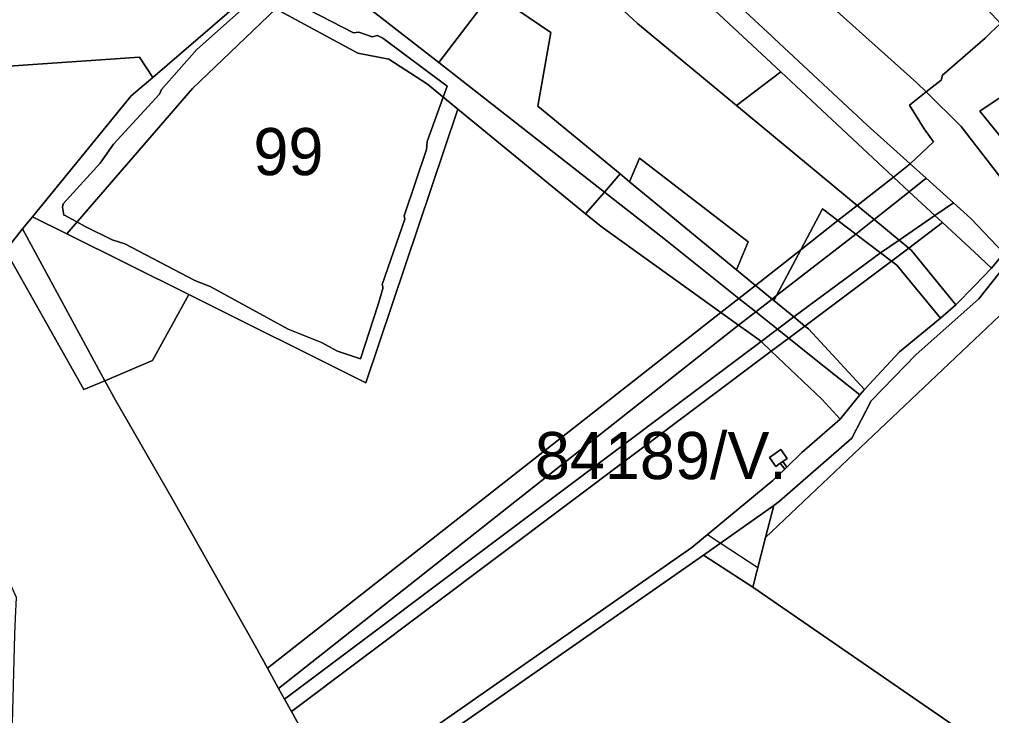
# Model space of a CAD drawing. Extents: x -477304 to -465429, y -1159113 to -1149210.
# Drawn here: x -474718.2 to -474408.5, y -1155444.6 to -1155222.8 of the extents above; entities that cross this region are included whole.
import ezdxf

# ---------------------------------------------------------------- set-up
doc = ezdxf.new("R2010")
doc.units = 0
for name, color, linetype in [('BPEJ_s', 7, 'Continuous'), ('ostatni_s', 7, 'Continuous'), ('PUPFL_s', 7, 'Continuous'), ('trav_porost_s', 7, 'Continuous')]:
    doc.layers.add(name, color=color, linetype=linetype)

msp = doc.modelspace()

# ---------------------------------------------------------------- linework, layer by layer
at = {"layer": 'BPEJ_s'}
for points in [[(-474633.02, -1155216.01), (-474611.78, -1155227.06), (-474610.08, -1155226.85), (-474605.83, -1155228.34), (-474604.12, -1155227.91), (-474602.42, -1155228.76), (-474582.01, -1155244.07), (-474582.86, -1155246.41), (-474583.26, -1155247.51), (-474588.39, -1155261.72), (-474588.6, -1155264.27), (-474595.62, -1155285.32), (-474595.41, -1155286.39), (-474602.64, -1155307.23), (-474602.51, -1155307.96), (-474602.42, -1155308.5), (-474603.91, -1155313.61), (-474609.59, -1155330.92), (-474616.88, -1155328.49), (-474618.3, -1155327.72), (-474621.99, -1155325.73), (-474632.62, -1155321.47), (-474657.5, -1155307.86), (-474662.14, -1155306.05), (-474662.39, -1155305.95), (-474684.71, -1155294.26), (-474688.75, -1155292.98), (-474697.26, -1155288.73), (-474699.92, -1155287.31), (-474703.92, -1155285.19), (-474704.07, -1155285.11), (-474704.49, -1155282.56), (-474704.28, -1155281.5), (-474692.58, -1155268.53), (-474688.33, -1155262.57), (-474673.66, -1155246.62), (-474673.02, -1155245.14), (-474661.75, -1155232.38), (-474643.67, -1155216.22)], [(-474643.67, -1155216.22), (-474661.75, -1155232.38), (-474673.02, -1155245.14), (-474673.66, -1155246.62), (-474688.33, -1155262.57), (-474692.58, -1155268.53), (-474704.28, -1155281.5), (-474704.49, -1155282.56), (-474704.07, -1155285.11), (-474703.92, -1155285.19), (-474699.92, -1155287.31), (-474697.26, -1155288.73), (-474688.75, -1155292.98), (-474684.71, -1155294.26), (-474662.39, -1155305.95), (-474662.14, -1155306.05), (-474657.5, -1155307.86), (-474632.62, -1155321.47), (-474621.99, -1155325.73), (-474618.3, -1155327.72), (-474616.88, -1155328.49), (-474609.59, -1155330.92), (-474603.91, -1155313.61), (-474602.42, -1155308.5), (-474602.51, -1155307.96), (-474602.64, -1155307.23), (-474595.41, -1155286.39), (-474595.62, -1155285.32), (-474588.6, -1155264.27), (-474588.39, -1155261.72), (-474583.26, -1155247.51), (-474582.86, -1155246.41), (-474582.01, -1155244.07), (-474602.42, -1155228.76), (-474604.12, -1155227.91), (-474605.83, -1155228.34), (-474610.08, -1155226.85), (-474611.78, -1155227.06), (-474633.02, -1155216.01)], [(-474417.31, -1155450.02), (-474484.54, -1155403.64), (-474482.99, -1155397.54), (-474494.95, -1155389.66), (-474499.03, -1155386.97), (-474504.01, -1155391.09), (-474616.93, -1155469.81)], [(-474417.31, -1155450.02), (-474484.54, -1155403.64), (-474482.99, -1155397.54), (-474494.95, -1155389.66), (-474499.03, -1155386.97), (-474504.01, -1155391.09), (-474616.93, -1155469.81)]]:
    msp.add_lwpolyline(points, dxfattribs=at)
at = {"layer": 'ostatni_s'}
for points in [[(-474514.39, -1155194.75), (-474478.44, -1155228.23), (-474477.78, -1155228.85), (-474448.17, -1155256.43), (-474434.41, -1155268.84), (-474439.73, -1155273.01), (-474475.69, -1155239.5), (-474546.75, -1155173.3)], [(-474559.58, -1155203.62), (-474584.6, -1155236.46), (-474623.05, -1155206.52)], [(-474399.99, -1155295.96), (-474412.54, -1155311.85), (-474432.54, -1155329.55), (-474446.85, -1155344.35), (-474453, -1155356.18), (-474476.08, -1155376.32), (-474477.93, -1155377.63), (-474500.29, -1155393.44), (-474617.09, -1155474.92)], [(-474616.93, -1155469.81), (-474504.01, -1155391.09), (-474478.15, -1155369.7), (-474474.43, -1155366.08), (-474473.77, -1155365.43), (-474468.94, -1155360.73), (-474456.75, -1155350.11), (-474450.44, -1155342.37), (-474449.02, -1155340.65), (-474437.82, -1155328.69), (-474424.8, -1155318.02), (-474419.9, -1155313.7), (-474414.09, -1155307.77), (-474408.52, -1155302.08), (-474404.57, -1155297.29)]]:
    msp.add_lwpolyline(points, dxfattribs=at)
for points in [[(-474505.35, -1155201.7), (-474492.27, -1155192.8), (-474470.07, -1155209.07), (-474432.29, -1155243), (-474429.36, -1155245.9), (-474434.68, -1155250.07), (-474430.02, -1155257.61), (-474427.01, -1155261.81), (-474434.41, -1155268.84), (-474448.17, -1155256.43), (-474477.78, -1155228.85), (-474478.44, -1155228.23), (-474514.39, -1155194.75)], [(-474548.92, -1155226.98), (-474563.35, -1155217.17), (-474559.58, -1155203.62), (-474553.09, -1155194.57), (-474521.28, -1155224.08), (-474489.79, -1155250.18), (-474451.3, -1155282.07), (-474457.45, -1155286.9), (-474462.4, -1155283.13), (-474469.29, -1155296.17), (-474483.75, -1155307.51), (-474489.73, -1155302.59), (-474486.07, -1155293.66), (-474520.65, -1155267.01), (-474523.86, -1155274.48), (-474526.88, -1155271.99), (-474553.07, -1155250.42)], [(-474600.54, -1155235.44), (-474610.39, -1155233.51), (-474636.57, -1155219.42), (-474623.05, -1155206.52), (-474584.6, -1155236.46), (-474531.87, -1155277.78), (-474537.85, -1155284.72), (-474578.57, -1155251.35), (-474588.21, -1155243.45)], [(-474420.67, -1155281.24), (-474429.36, -1155273.41), (-474434.41, -1155268.84), (-474427.01, -1155261.81), (-474430.02, -1155257.61), (-474434.68, -1155250.07), (-474429.36, -1155245.9), (-474418.22, -1155256.91), (-474395.5, -1155286.28), (-474404.57, -1155297.29), (-474415.15, -1155286.23)], [(-474434.41, -1155268.84), (-474429.36, -1155273.41), (-474434.72, -1155277.67), (-474439.73, -1155273.01)], [(-474429.36, -1155273.41), (-474420.67, -1155281.24), (-474426.56, -1155285.28), (-474434.72, -1155277.67)], [(-474532.86, -1155288.81), (-474537.85, -1155284.72), (-474531.87, -1155277.78), (-474512.94, -1155292.62), (-474489.04, -1155311.67), (-474494.73, -1155316.13)], [(-474445.91, -1155286.54), (-474451.8, -1155291.19), (-474457.45, -1155286.9), (-474451.3, -1155282.07)], [(-474404.57, -1155297.29), (-474408.52, -1155302.08), (-474412.05, -1155298.79), (-474412.51, -1155298.37), (-474424.18, -1155287.49), (-474426.56, -1155285.28), (-474420.67, -1155281.24), (-474415.15, -1155286.23)], [(-474717.31, -1155289.5), (-474714.14, -1155285.63), (-474703.18, -1155291.09), (-474664.33, -1155310.46), (-474675.82, -1155331.5), (-474691, -1155337.91)], [(-474443.94, -1155297.16), (-474451.8, -1155291.19), (-474445.91, -1155286.54), (-474438, -1155293.09)], [(-474432.54, -1155329.55), (-474412.54, -1155311.85), (-474399.99, -1155295.96), (-474387.54, -1155299.8), (-474395.78, -1155307.6), (-474480.52, -1155387.83), (-474477.93, -1155377.63), (-474476.08, -1155376.32), (-474453, -1155356.18), (-474446.85, -1155344.35)], [(-474434.91, -1155295.65), (-474440.43, -1155299.83), (-474443.94, -1155297.16), (-474438, -1155293.09)], [(-474434.91, -1155295.65), (-474434.06, -1155296.36), (-474419.9, -1155313.7), (-474424.8, -1155318.02), (-474438.72, -1155301.13), (-474440.43, -1155299.83)], [(-474483.75, -1155307.51), (-474469.29, -1155296.17), (-474477, -1155310.79), (-474478.43, -1155311.9)], [(-474477, -1155310.79), (-474477.84, -1155312.38), (-474478.43, -1155311.9)], [(-474489.04, -1155311.67), (-474483.66, -1155315.96), (-474489.09, -1155320.16), (-474494.73, -1155316.13)], [(-474482.54, -1155324.86), (-474489.09, -1155320.16), (-474483.66, -1155315.96), (-474476.73, -1155321.49), (-474481.97, -1155325.4)], [(-474476.73, -1155321.49), (-474473.13, -1155324.35), (-474478.68, -1155328.52), (-474481.97, -1155325.4)], [(-474456.75, -1155350.11), (-474462.6, -1155343.75), (-474478.68, -1155328.52), (-474473.13, -1155324.35), (-474465.97, -1155330.06), (-474450.44, -1155342.37)], [(-474473.65, -1155362.67), (-474475.03, -1155363.64), (-474475.82, -1155364.21), (-474477.22, -1155365.2), (-474479.29, -1155362.33), (-474475.7, -1155359.78)]]:
    msp.add_lwpolyline(points, close=True, dxfattribs=at)
at = {"layer": 'PUPFL_s'}
msp.add_lwpolyline([(-474744.11, -1155102.65), (-474699.91, -1155140.43), (-474662.66, -1155122.9), (-474649.82, -1155112.36), (-474635.13, -1155088.02), (-474614.26, -1155094.23), (-474597.01, -1155110.7), (-474591.41, -1155108.16), (-474574.47, -1155122.56), (-474552.82, -1155115.18), (-474539.57, -1155124.05), (-474675.73, -1155241.25), (-474680.02, -1155234.83), (-474726.43, -1155238.04)], dxfattribs=at)
for points in [[(-474663.13, -1155244.76), (-474703.18, -1155291.09), (-474714.14, -1155285.63), (-474682.6, -1155247.08), (-474675.73, -1155241.25), (-474539.57, -1155124.05), (-474521.62, -1155125.68), (-474529.18, -1155132.56), (-474575.07, -1155169.14), (-474623.05, -1155206.52), (-474636.57, -1155219.42)], [(-474584.6, -1155236.46), (-474559.58, -1155203.62), (-474563.35, -1155217.17), (-474548.92, -1155226.98), (-474553.07, -1155250.42), (-474526.88, -1155271.99), (-474531.87, -1155277.78)], [(-474607.85, -1155338.62), (-474664.33, -1155310.46), (-474703.18, -1155291.09), (-474663.13, -1155244.76), (-474636.57, -1155219.42), (-474610.39, -1155233.51), (-474600.54, -1155235.44), (-474588.21, -1155243.45), (-474578.57, -1155251.35)], [(-474486.07, -1155293.66), (-474489.73, -1155302.59), (-474523.86, -1155274.48), (-474520.65, -1155267.01)], [(-474523.86, -1155274.48), (-474489.73, -1155302.59), (-474483.75, -1155307.51), (-474489.04, -1155311.67), (-474512.94, -1155292.62), (-474531.87, -1155277.78), (-474526.88, -1155271.99)], [(-474691, -1155337.91), (-474697.73, -1155340.75), (-474722.72, -1155296.37), (-474717.31, -1155289.5)], [(-474483.75, -1155307.51), (-474478.43, -1155311.9), (-474483.66, -1155315.96), (-474489.04, -1155311.67)], [(-474476.73, -1155321.49), (-474483.66, -1155315.96), (-474478.43, -1155311.9), (-474477.84, -1155312.38), (-474471.51, -1155317.59)], [(-474471.51, -1155317.59), (-474467.97, -1155320.51), (-474473.13, -1155324.35), (-474476.73, -1155321.49)], [(-474467.97, -1155320.51), (-474466.87, -1155321.42), (-474449.02, -1155340.65), (-474450.44, -1155342.37), (-474465.97, -1155330.06), (-474473.13, -1155324.35)], [(-474500.29, -1155393.44), (-474477.93, -1155377.63), (-474480.52, -1155387.83), (-474484.54, -1155403.64)], [(-474617.09, -1155474.92), (-474500.29, -1155393.44), (-474484.54, -1155403.64), (-474412.53, -1155453.32), (-474430.52, -1155480.62), (-474441.09, -1155497.42), (-474472.72, -1155547.69), (-474500.15, -1155517.45), (-474521.65, -1155502.2), (-474522.11, -1155494.83), (-474624.42, -1155549.1), (-474626.53, -1155550.24), (-474639.01, -1155537.09), (-474692.67, -1155587.82), (-474723.24, -1155550.86), (-474722.04, -1155506.28)]]:
    msp.add_lwpolyline(points, close=True, dxfattribs=at)
at = {"layer": 'trav_porost_s'}
for points in [[(-474508.32, -1155136.87), (-474476.73, -1155150.13), (-474450.86, -1155156.98), (-474449.15, -1155157.3), (-474435.47, -1155169.4), (-474424.23, -1155184.8), (-474425.81, -1155176.61), (-474419.98, -1155183.7), (-474409.81, -1155219.67), (-474405.7, -1155224.09), (-474408.81, -1155227), (-474410.57, -1155228.74), (-474424.17, -1155240.52), (-474424.55, -1155242.13), (-474429.36, -1155245.9), (-474432.29, -1155243), (-474470.07, -1155209.07), (-474492.27, -1155192.8), (-474531.7, -1155163.91)], [(-474521.28, -1155224.08), (-474553.09, -1155194.57), (-474564.08, -1155184.1), (-474554.16, -1155177.92), (-474546.75, -1155173.3), (-474475.69, -1155239.5), (-474489.79, -1155250.18)], [(-474376.81, -1155262.03), (-474391.19, -1155281.05), (-474395.5, -1155286.28), (-474418.22, -1155256.91), (-474429.36, -1155245.9), (-474424.55, -1155242.13), (-474424.17, -1155240.52), (-474410.57, -1155228.74), (-474408.81, -1155227), (-474405.7, -1155224.09), (-474392.24, -1155238.58), (-474412.2, -1155252), (-474393.93, -1155274.52), (-474384.36, -1155266.09), (-474371, -1155254.34)], [(-474714.14, -1155285.63), (-474717.31, -1155289.5), (-474722.72, -1155296.37), (-474754.01, -1155336.25), (-474760.15, -1155248.35), (-474726.43, -1155238.04), (-474680.02, -1155234.83), (-474675.73, -1155241.25), (-474682.6, -1155247.08)], [(-474393.93, -1155274.52), (-474412.2, -1155252), (-474392.24, -1155238.58), (-474390.11, -1155237.15), (-474400.3, -1155248.99), (-474402.23, -1155251.23), (-474397.82, -1155254.89), (-474393.21, -1155258.73), (-474387.09, -1155263.82), (-474384.36, -1155266.09)], [(-474439.73, -1155273.01), (-474451.3, -1155282.07), (-474489.79, -1155250.18), (-474475.69, -1155239.5)], [(-474687.63, -1155344.12), (-474691, -1155337.91), (-474675.82, -1155331.5), (-474664.33, -1155310.46), (-474607.85, -1155338.62), (-474578.57, -1155251.35), (-474537.85, -1155284.72), (-474532.86, -1155288.81), (-474494.73, -1155316.13), (-474639.26, -1155429.52), (-474643.19, -1155422.42), (-474669.53, -1155375.69)], [(-474434.72, -1155277.67), (-474445.91, -1155286.54), (-474451.3, -1155282.07), (-474439.73, -1155273.01)], [(-474426.56, -1155285.28), (-474438, -1155293.09), (-474445.91, -1155286.54), (-474434.72, -1155277.67)], [(-474462.4, -1155283.13), (-474457.45, -1155286.9), (-474469.29, -1155296.17)], [(-474424.18, -1155287.49), (-474434.91, -1155295.65), (-474438, -1155293.09), (-474426.56, -1155285.28)], [(-474457.45, -1155286.9), (-474451.8, -1155291.19), (-474477, -1155310.79), (-474469.29, -1155296.17)], [(-474412.51, -1155298.37), (-474412.05, -1155298.79), (-474408.52, -1155302.08), (-474414.09, -1155307.77), (-474419.9, -1155313.7), (-474434.06, -1155296.36), (-474434.91, -1155295.65), (-474424.18, -1155287.49)], [(-474443.94, -1155297.16), (-474471.51, -1155317.59), (-474477.84, -1155312.38), (-474477, -1155310.79), (-474451.8, -1155291.19)], [(-474724.73, -1155395), (-474752.87, -1155353.45), (-474754.01, -1155336.25), (-474722.72, -1155296.37), (-474697.73, -1155340.75), (-474691, -1155337.91), (-474687.63, -1155344.12), (-474669.53, -1155375.69), (-474643.19, -1155422.42), (-474639.26, -1155429.52), (-474635.67, -1155435.99), (-474633.77, -1155439.42), (-474631.61, -1155443.32), (-474616.93, -1155469.81), (-474618.23, -1155470.72), (-474721.93, -1155502.37), (-474721.75, -1155495.62), (-474719.68, -1155418.74), (-474719.55, -1155413.56), (-474719.19, -1155406.97)], [(-474443.94, -1155297.16), (-474440.43, -1155299.83), (-474467.97, -1155320.51), (-474471.51, -1155317.59)], [(-474467.97, -1155320.51), (-474440.43, -1155299.83), (-474438.72, -1155301.13), (-474424.8, -1155318.02), (-474437.82, -1155328.69), (-474449.02, -1155340.65), (-474466.87, -1155321.42)], [(-474639.26, -1155429.52), (-474494.73, -1155316.13), (-474489.09, -1155320.16), (-474635.67, -1155435.99)], [(-474633.77, -1155439.42), (-474635.67, -1155435.99), (-474489.09, -1155320.16), (-474482.54, -1155324.86), (-474481.97, -1155325.4)], [(-474478.68, -1155328.52), (-474631.61, -1155443.32), (-474633.77, -1155439.42), (-474481.97, -1155325.4)], [(-474475.82, -1155364.21), (-474474.43, -1155366.08), (-474478.15, -1155369.7), (-474504.01, -1155391.09), (-474616.93, -1155469.81), (-474631.61, -1155443.32), (-474478.68, -1155328.52), (-474462.6, -1155343.75), (-474456.75, -1155350.11), (-474468.94, -1155360.73), (-474473.77, -1155365.43), (-474475.03, -1155363.64), (-474473.65, -1155362.67), (-474475.7, -1155359.78), (-474479.29, -1155362.33), (-474477.22, -1155365.2)], [(-474474.43, -1155366.08), (-474475.82, -1155364.21), (-474475.03, -1155363.64), (-474473.77, -1155365.43)]]:
    msp.add_lwpolyline(points, close=True, dxfattribs=at)
msp.add_lwpolyline([(-474412.53, -1155453.32), (-474484.54, -1155403.64), (-474480.52, -1155387.83), (-474395.78, -1155307.6), (-474355.26, -1155319.34), (-474357.29, -1155330.67), (-474359.16, -1155330.45), (-474364.96, -1155358.86), (-474371.73, -1155357.13), (-474387.58, -1155458.32)], dxfattribs=at)

# ---------------------------------------------------------------- texts
at = {"layer": 'BPEJ_s'}
for s, p in [('99', (-474643.69, -1155272.4)), ('84189/V.', (-474554.03, -1155369.25))]:
    msp.add_text(s, height=15, dxfattribs=at).set_placement(p)

doc.saveas('drawing.dxf')
